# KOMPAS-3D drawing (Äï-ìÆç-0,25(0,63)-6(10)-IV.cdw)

Views: Вид 1, Спереди 2, Проекционный вид 3, Спереди 4, Проекционный вид 5, Проекционный вид 6, Проекционный вид 7, Проекционный вид 8, Проекционный вид 9, Изометрия XYZ 10, Вид 11, Вид 12, Вид 13, Спереди 14, Проекционный вид 15, Проекционный вид 16, Проекционный вид 17, Проекционный вид 18, Проекционный вид 19, Изометрия XYZ 20, Проекционный вид 22, Проекционный вид 23, Проекционный вид 25, Вид 26, Вид 27, Вид 28
Referenced files: GRAPHIC.TDP
Referenced files in Y:\Технический отдел\КБ\Рабочая папка\КД\Тр-ры наружной установки\Тр-ры силовые\ОЛ-НТЗ-6(10)-IV УХЛ1 от 25.10.14\Чертежи\: Трансформатор ОЛ  НТЗ.24.01.00.00.000 ГЧ.cdw
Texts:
  Body Specificaton ( centered )
  Body Specification ( left align )
  Title Specification
  Материал-Предприятие
  Лит-Масса-Масштаб
  Контакт М8
  Ввод кабельный М16
  Контакт
  заземления М10
  Крышка
  защитная
  Винт М4х16
  max
  Табличка технических
  данных
  ГОСТ 52719-2007
  Маркировка
  Масса, не более 25 кг
  ОЛ-НТЗ-0,63/6(10)-IV
  Защитная крышка условно не показана
  Винт М6
  Шайба A. 6.37 ГОСТ 11371-78
  Шайба
  .Ти9
  ГОСТ
  АД1 ГОСТ 4784-97
  Шайба 6 Л ГОСТ 6402-70
  Шайба пружинная
  Винт А.М 4-6g x 35-22 ГОСТ 1491-80
  Винт обычный
  Винт
  Винт А.М 6-6g x 10 ГОСТ 1491-80
  Шайба210 Л ГОСТ 6402-70
  Болт М10-6g x 10 ГОСТ 7796-70
  Болт
  Шайба A. 10.37 ГОСТ 11371-78
  Поз.
  Кол.
  Приме-
  чание
  Таблица спецификации
  Трансформатор силовой малой мощности
  ОЛ-НТЗ-1,25/6(10)-IV УХЛ1, Т1
  Габаритный чертеж
  М.контр.
  НТЗ
  Михайлов
  Пимурзин
  Морозов
  Бадулин
  Фролова
  НТЗ.24.01.00.00.000
  Без оформления
Dimensions and other numbers on the sheet: 243; 2 шт.; 4 шт.; 381; 351; 177; 306; 96; 10; 4 отв.; 54; 25; 38; 28; 6 шт.; 4; 1; 78; 65Г; 029; 70; -6g; -22; 80; 2; 37; 1:4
